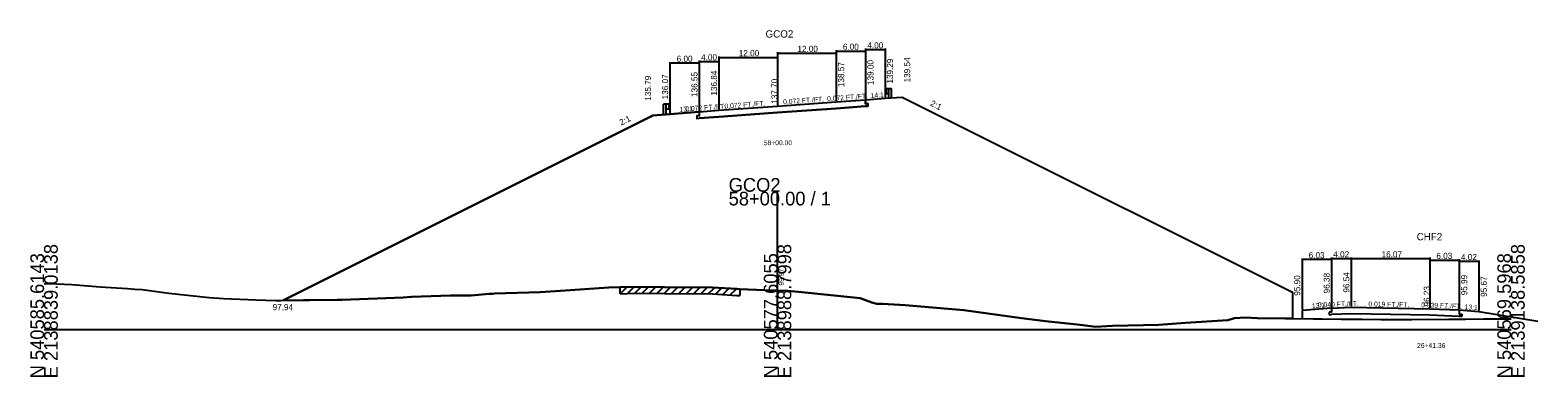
# Model space of a CAD drawing. Extents: x -14327 to 8886, y -10 to 39048.
# Drawn here: x 1997.2 to 2305.5, y 15990.3 to 16061.2 of the extents above; entities that cross this region are included whole.
import ezdxf

# ---------------------------------------------------------------- set-up
doc = ezdxf.new("R2010")
doc.units = 0
for name, color, linetype in [('Level 1', 7, 'Continuous'), ('Level 20', 7, 'Continuous'), ('Level 5', 7, 'Continuous'), ('Level 53', 7, 'Continuous'), ('Level 54', 7, 'Continuous'), ('Level 55', 7, 'Continuous'), ('Level 7', 7, 'Continuous'), ('RD_GPK_XS_Cell', 7, 'Continuous'), ('RD_XS_EwShp', 7, 'Continuous'), ('RD_XS_ExGround', 7, 'Continuous'), ('RD_XS_ExPaveRet', 7, 'Continuous'), ('RD_XS_Pave', 7, 'Continuous'), ('RD_XS_TX_Baseline', 7, 'Continuous'), ('RD_XS_TX_Elev_EX', 7, 'Continuous'), ('RD_XS_TX_Elev_PR', 7, 'Continuous'), ('RD_XS_TX_Station', 7, 'Continuous')]:
    doc.layers.add(name, color=color, linetype=linetype)

msp = doc.modelspace()

# ---------------------------------------------------------------- linework, layer by layer
at = {"layer": 'Level 1'}
for p, q in [((2172.02, 16049.1), (2172.14, 16049.2)), ((2172.02, 16049), (2172.14, 16048.91)), ((2172.02, 16048.57), (2172.14, 16048.67)), ((2172.15, 16049.2), (2172.23, 16049.21)), ((2172.16, 16048.87), (2172.16, 16048.71)), ((2172.23, 16049.27), (2172.23, 16048.3)), ((2172.23, 16049.27), (2172.78, 16049.27)), ((2172.78, 16047.29), (2172.78, 16049.27)), ((2172.78, 16049.27), (2173.34, 16049.27)), ((2173.34, 16047.29), (2173.34, 16049.27)), ((2126.66, 16044.07), (2126.66, 16046.06)), ((2127.22, 16046.06), (2126.66, 16046.06)), ((2127.22, 16044.07), (2127.22, 16046.06)), ((2127.77, 16046.06), (2127.22, 16046.06)), ((2127.77, 16046.06), (2127.77, 16045.09)), ((2127.85, 16045.99), (2127.77, 16046)), ((2127.84, 16045.65), (2127.84, 16045.5)), ((2127.98, 16045.89), (2127.86, 16045.98)), ((2127.98, 16045.79), (2127.86, 16045.7)), ((2127.98, 16045.36), (2127.86, 16045.45)), ((2172.02, 16048.47), (2172.14, 16048.38)), ((2172.15, 16048.38), (2172.23, 16048.36)), ((2172.23, 16048.3), (2172.78, 16048.3)), ((2127.77, 16045.09), (2127.22, 16045.09)), ((2127.85, 16045.16), (2127.77, 16045.15)), ((2127.98, 16045.26), (2127.86, 16045.17))]:
    msp.add_line(p, q, dxfattribs=at)
for centre, radius, start, end in [((2172.07, 16049.05), 0.0651, 129.0336, 230.9663), ((2172.07, 16048.52), 0.0651, 129.0336, 230.9663), ((2172.09, 16048.71), 0.0651, 302.9895, 0), ((2172.15, 16049.18), 0.026, 90, 129.0505), ((2172.09, 16048.87), 0.0651, 0, 45), ((2127.91, 16045.65), 0.0651, 135, 180), ((2127.91, 16045.5), 0.0651, 180, 237.0105), ((2127.85, 16045.96), 0.026, 50.9495, 90), ((2127.93, 16045.84), 0.0651, 309.0337, 50.9664), ((2172.15, 16048.4), 0.026, 230.9496, 270), ((2127.85, 16045.19), 0.026, 270, 309.0504), ((2127.93, 16045.31), 0.0651, 309.0337, 50.9664)]:
    msp.add_arc(centre, radius, start, end, dxfattribs=at)
at = {"layer": 'Level 20'}
for p, q in [((2263.31, 16014.69), (2263.31, 16004.58)), ((2267.33, 16014.69), (2267.33, 16004.74)), ((2283.39, 16014.69), (2283.39, 16004.43)), ((2257.28, 16014.53), (2257.28, 16004.1)), ((2263.31, 16014.33), (2257.28, 16014.33)), ((2263.31, 16014.53), (2263.31, 16004.58)), ((2263.31, 16014.49), (2267.33, 16014.49)), ((2267.33, 16014.49), (2283.39, 16014.49)), ((2283.39, 16014.38), (2283.39, 16004.43)), ((2283.39, 16014.18), (2289.42, 16014.18)), ((2289.42, 16014.38), (2289.42, 16004.19)), ((2289.42, 16014.14), (2289.42, 16004.19)), ((2289.42, 16013.94), (2293.44, 16013.94)), ((2293.44, 16014.14), (2293.44, 16003.87)), ((2263.31, 16004.38), (2257.28, 16003.9)), ((2257.28, 16003.9), (2257.28, 16002.19)), ((2263.31, 16003.54), (2262.81, 16003.52)), ((2262.81, 16003.52), (2262.81, 16003.02)), ((2262.81, 16003.02), (2263.31, 16003.04)), ((2263.31, 16004.38), (2267.33, 16004.54)), ((2263.31, 16004.38), (2263.31, 16003.54)), ((2267.33, 16003.21), (2263.31, 16003.04)), ((2267.33, 16004.54), (2283.39, 16004.23)), ((2283.39, 16002.9), (2267.33, 16003.21)), ((2283.39, 16004.23), (2289.42, 16003.99)), ((2289.42, 16002.66), (2283.39, 16002.9)), ((2289.42, 16003.99), (2289.42, 16003.16)), ((2289.42, 16003.99), (2293.44, 16003.67)), ((2289.42, 16003.16), (2289.92, 16003.14)), ((2289.92, 16002.64), (2289.42, 16002.66)), ((2289.92, 16003.14), (2289.92, 16002.64)), ((2293.44, 16003.67), (2305.49, 16001.67))]:
    msp.add_line(p, q, dxfattribs=at)
at = {"layer": 'Level 5'}
for p, q in [((2168, 16045.67), (2162, 16045.23)), ((2168, 16047), (2168, 16046.17)), ((2168, 16046.17), (2168.5, 16046.2)), ((2168.5, 16045.7), (2168, 16045.67)), ((2168.5, 16046.2), (2168.5, 16045.7)), ((2134, 16043.72), (2133.5, 16043.68)), ((2133.5, 16043.68), (2133.5, 16043.18)), ((2133.5, 16043.18), (2134, 16043.22)), ((2134, 16044.55), (2134, 16043.72)), ((2138, 16043.51), (2134, 16043.22)), ((2150, 16044.37), (2138, 16043.51)), ((2162, 16045.23), (2150, 16044.37))]:
    msp.add_line(p, q, dxfattribs=at)
at = {"layer": 'Level 54'}
for p, q in [((2128, 16054.7), (2128, 16044.27)), ((2134, 16054.99), (2134, 16044.75)), ((2134, 16054.79), (2138, 16054.79)), ((2134, 16054.7), (2134, 16044.75)), ((2138, 16055.85), (2138, 16045.04)), ((2138, 16055.65), (2150, 16055.65)), ((2138, 16054.99), (2138, 16045.04)), ((2150, 16056.72), (2150, 16045.9)), ((2150, 16056.52), (2162, 16056.52)), ((2150, 16055.85), (2150, 16045.9)), ((2162, 16057.15), (2162, 16046.77)), ((2162, 16056.95), (2168, 16056.95)), ((2162, 16056.72), (2162, 16046.77)), ((2168, 16057.44), (2168, 16047.2)), ((2168, 16057.24), (2172, 16057.24)), ((2168, 16057.15), (2168, 16047.2)), ((2172, 16057.44), (2172, 16047.49)), ((2134, 16054.5), (2128, 16054.5))]:
    msp.add_line(p, q, dxfattribs=at)
at = {"layer": 'Level 7'}
for p, q in [((2168, 16047), (2172, 16047.29)), ((2172, 16047.29), (2175.5, 16047.54)), ((2175.5, 16047.54), (2187.5, 16041.54)), ((2124.5, 16043.79), (2112.5, 16037.79)), ((2128, 16044.07), (2124.5, 16043.79)), ((2134, 16044.55), (2128, 16044.07)), ((2187.5, 16041.54), (2255.28, 16007.65)), ((2112.5, 16037.79), (2048.8, 16005.94)), ((2255.28, 16007.65), (2255.28, 16002.21))]:
    msp.add_line(p, q, dxfattribs=at)
at = {"layer": 'RD_GPK_XS_Cell'}
for p, q in [((2150, 16000), (2150, 16028.17)), ((2000, 16000), (2150, 16000)), ((2150, 16000), (2300, 16000))]:
    msp.add_line(p, q, dxfattribs=at)
at = {"layer": 'RD_XS_EwShp'}
msp.add_lwpolyline([(2134, 16044.55), (2134, 16043.72), (2133.5, 16043.68), (2133.5, 16043.18), (2134, 16043.22), (2138, 16043.51), (2150, 16044.37), (2162, 16045.23), (2168, 16045.67), (2168.5, 16045.7), (2168.5, 16046.2), (2168, 16046.17), (2168, 16047), (2172, 16047.29), (2175.5, 16047.54), (2187.5, 16041.54), (2255.28, 16007.65), (2255.28, 16002.21), (2248.11, 16002.28), (2245.69, 16002.45), (2243.42, 16002.33), (2242.06, 16001.91), (2233.44, 16001.35), (2230.73, 16001.17), (2228, 16000.95), (2218.49, 16000.71), (2215, 16000.56), (2214.54, 16000.6), (2211.89, 16000.93), (2204.78, 16001.68), (2199.87, 16002.29), (2188.09, 16003.95), (2176.13, 16004.94), (2171.44, 16005.22), (2170.32, 16005.21), (2169.3, 16005.52), (2168, 16006), (2166.92, 16006.37), (2154.31, 16007.67), (2152.01, 16007.89), (2150, 16007.97), (2147.39, 16008.07), (2142.31, 16008.26), (2141.69, 16008.28), (2136.69, 16008.56), (2126.91, 16008.67), (2120.66, 16008.74), (2117.81, 16008.62), (2115.49, 16008.6), (2105.63, 16007.93), (2101.43, 16007.62), (2092.14, 16007.33), (2091.72, 16007.32), (2091, 16007.28), (2087.37, 16006.98), (2084.75, 16006.96), (2083.13, 16006.97), (2075.14, 16006.66), (2073.41, 16006.56), (2060.96, 16006.07), (2059.94, 16006.06), (2054.31, 16006.02), (2053.03, 16005.98), (2048.8, 16005.94), (2112.5, 16037.79), (2124.5, 16043.79), (2128, 16044.07)], close=True, dxfattribs=at)
at = {"layer": 'RD_XS_ExGround'}
for p, q in [((2000, 16009.39), (2002.61, 16009.32)), ((2002.61, 16009.32), (2005.7, 16009.22)), ((2005.7, 16009.22), (2011.45, 16008.72)), ((2011.45, 16008.72), (2017.05, 16008.37)), ((2105.63, 16007.93), (2115.49, 16008.6)), ((2115.49, 16008.6), (2117.81, 16008.62)), ((2117.81, 16008.62), (2120.66, 16008.74)), ((2120.66, 16008.74), (2126.91, 16008.67)), ((2126.91, 16008.67), (2136.69, 16008.56)), ((2136.69, 16008.56), (2141.69, 16008.28)), ((2017.05, 16008.37), (2018.59, 16008.27)), ((2018.59, 16008.27), (2020.08, 16008.15)), ((2020.08, 16008.15), (2025.51, 16007.42)), ((2025.51, 16007.42), (2033.75, 16006.53)), ((2033.75, 16006.53), (2036.72, 16006.32)), ((2036.72, 16006.32), (2043.3, 16006.07)), ((2043.3, 16006.07), (2047.39, 16005.94)), ((2047.39, 16005.94), (2048.41, 16005.94)), ((2048.41, 16005.94), (2053.03, 16005.98)), ((2053.03, 16005.98), (2054.31, 16006.02)), ((2054.31, 16006.02), (2059.94, 16006.06)), ((2059.94, 16006.06), (2060.96, 16006.07)), ((2060.96, 16006.07), (2073.41, 16006.56)), ((2073.41, 16006.56), (2075.14, 16006.66)), ((2075.14, 16006.66), (2083.13, 16006.97)), ((2083.13, 16006.97), (2084.75, 16006.96)), ((2084.75, 16006.96), (2087.37, 16006.98)), ((2087.37, 16006.98), (2091, 16007.28)), ((2091, 16007.28), (2091.72, 16007.32)), ((2091.72, 16007.32), (2092.14, 16007.33)), ((2092.14, 16007.33), (2101.43, 16007.62)), ((2101.43, 16007.62), (2105.63, 16007.93)), ((2141.69, 16008.28), (2142.31, 16008.26)), ((2142.31, 16008.26), (2147.39, 16008.07)), ((2147.39, 16008.07), (2150, 16007.97)), ((2150, 16007.97), (2152.01, 16007.89)), ((2152.01, 16007.89), (2154.31, 16007.67)), ((2154.31, 16007.67), (2166.92, 16006.37)), ((2166.92, 16006.37), (2168, 16006)), ((2168, 16006), (2169.3, 16005.52)), ((2169.3, 16005.52), (2170.32, 16005.21)), ((2170.32, 16005.21), (2171.44, 16005.22)), ((2171.44, 16005.22), (2176.13, 16004.94)), ((2176.13, 16004.94), (2188.09, 16003.95)), ((2188.09, 16003.95), (2199.87, 16002.29)), ((2199.87, 16002.29), (2204.78, 16001.68)), ((2242.06, 16001.91), (2243.42, 16002.33)), ((2243.42, 16002.33), (2245.69, 16002.45)), ((2245.69, 16002.45), (2248.11, 16002.28)), ((2248.11, 16002.28), (2259.55, 16002.17)), ((2204.78, 16001.68), (2211.89, 16000.93)), ((2211.89, 16000.93), (2214.54, 16000.6)), ((2214.54, 16000.6), (2215, 16000.56)), ((2215, 16000.56), (2218.49, 16000.71)), ((2218.49, 16000.71), (2228, 16000.95)), ((2228, 16000.95), (2230.73, 16001.17)), ((2230.73, 16001.17), (2233.44, 16001.35)), ((2233.44, 16001.35), (2242.06, 16001.91)), ((2259.55, 16002.17), (2261.36, 16002.16)), ((2261.36, 16002.16), (2265.26, 16002.12)), ((2265.26, 16002.12), (2269.53, 16002.1)), ((2269.53, 16002.1), (2273.4, 16002.07)), ((2273.4, 16002.07), (2276.49, 16002.04)), ((2276.49, 16002.04), (2279.75, 16002.05)), ((2279.75, 16002.05), (2287.26, 16002.13)), ((2287.26, 16002.13), (2290.72, 16002.14)), ((2290.72, 16002.14), (2294.43, 16002.17)), ((2294.43, 16002.17), (2297.88, 16002.15)), ((2297.88, 16002.15), (2300, 16002.15))]:
    msp.add_line(p, q, dxfattribs=at)
at = {"layer": 'RD_XS_ExPaveRet'}
for p, q in [((2117.81, 16007.32), (2119.16, 16008.68)), ((2117.81, 16007.32), (2117.81, 16008.62)), ((2119.31, 16007.38), (2120.67, 16008.74)), ((2120.81, 16007.43), (2122.1, 16008.72)), ((2122.31, 16007.42), (2123.6, 16008.71)), ((2123.82, 16007.41), (2125.11, 16008.69)), ((2125.32, 16007.39), (2126.61, 16008.68)), ((2126.82, 16007.38), (2128.11, 16008.66)), ((2128.32, 16007.36), (2129.61, 16008.64)), ((2129.83, 16007.34), (2131.11, 16008.62)), ((2131.33, 16007.32), (2132.62, 16008.61)), ((2132.83, 16007.3), (2134.12, 16008.59)), ((2134.33, 16007.29), (2135.62, 16008.57)), ((2135.84, 16007.27), (2137.1, 16008.54)), ((2137.34, 16007.22), (2138.57, 16008.46)), ((2117.81, 16007.32), (2120.66, 16007.44)), ((2120.66, 16007.44), (2126.91, 16007.37)), ((2126.91, 16007.37), (2136.69, 16007.26)), ((2136.69, 16007.26), (2141.69, 16006.98)), ((2138.84, 16007.14), (2140.07, 16008.37)), ((2140.34, 16007.06), (2141.58, 16008.29)), ((2141.69, 16006.98), (2142.31, 16006.96)), ((2142.31, 16008.26), (2142.31, 16006.96))]:
    msp.add_line(p, q, dxfattribs=at)
at = {"layer": 'RD_XS_Pave'}
for p, q in [((2138, 16044.84), (2150, 16045.7)), ((2150, 16045.7), (2162, 16046.57)), ((2162, 16046.57), (2168, 16047)), ((2134, 16044.55), (2138, 16044.84))]:
    msp.add_line(p, q, dxfattribs=at)

# ---------------------------------------------------------------- texts
at = {"layer": 'Level 20'}
for s, height, p in [('CHF2', 1.5, (2280.71, 16018.23)), ('6.03', 1.25, (2258.62, 16014.58)), ('4.02', 1.25, (2263.65, 16014.74)), ('16.07', 1.25, (2273.53, 16014.74)), ('6.03', 1.25, (2284.73, 16014.43)), ('4.02', 1.25, (2289.76, 16014.19)), ('26+41.36', 1, (2280.78, 15996.23))]:
    msp.add_text(s, height=height, dxfattribs=at).set_placement(p)
for s, height, rotation, p in [('96.54', 1.25, 90, (2266.95, 16007.54)), ('95.90', 1.25, 90, (2256.9, 16006.9)), ('96.38', 1.25, 90, (2262.93, 16007.38)), (' 96.23', 1.25, 90, (2283.39, 16004.23)), ('95.99', 1.25, 90, (2291.05, 16006.99)), ('95.67', 1.25, 90, (2295.07, 16006.67)), ('13:1', 1, 4.5547, (2259.32, 16004.31)), ('0.040 FT./FT.', 1, 2.3104, (2260.54, 16004.52)), ('0.019 FT./FT.', 1, 358.8885, (2270.83, 16004.72)), ('0.039 FT./FT.', 1, 357.7484, (2281.62, 16004.55)), ('13:1', 1, 355.4453, (2290.49, 16004.16))]:
    msp.add_text(s, height=height, rotation=rotation, dxfattribs=at).set_placement(p)
at = {"layer": 'Level 53'}
for s, rotation, p in [('139.00', 90, (2169.63, 16050)), ('139.29', 90, (2173.63, 16050.29)), ('139.54', 90, (2177.13, 16050.54)), ('135.79', 90, (2124.13, 16046.79)), ('136.07', 90, (2127.63, 16047.07)), ('136.55', 90, (2133.63, 16047.55)), ('136.84', 90, (2137.63, 16047.84)), ('138.57', 90, (2163.63, 16049.57)), ('2:1', 333.4349, (2181.11, 16045.85)), ('2:1', 26.5651, (2118.05, 16041.69))]:
    msp.add_text(s, height=1.25, rotation=rotation, dxfattribs=at).set_placement(p)
msp.add_text('97.94', height=1.25, dxfattribs=at).set_placement((2046.74, 16003.94))
at = {"layer": 'Level 54'}
for s, p in [('12.00', (2154.07, 16056.77)), ('6.00', (2163.37, 16057.2)), ('4.00', (2168.37, 16057.49)), ('6.00', (2129.37, 16054.75)), ('4.00', (2134.37, 16055.04)), ('12.00', (2142.07, 16055.9))]:
    msp.add_text(s, height=1.25, dxfattribs=at).set_placement(p)
at = {"layer": 'Level 55'}
for s, rotation, p in [('13:1', 4.5739, (2130.03, 16044.48)), ('0.072 FT./FT.', 4.1182, (2131.18, 16044.6)), ('0.072 FT./FT.', 4.1182, (2139.18, 16045.18)), ('0.072 FT./FT.', 4.1182, (2151.18, 16046.04)), ('0.072 FT./FT.', 4.1182, (2160.18, 16046.69)), ('14:1', 4.1182, (2169.08, 16047.33))]:
    msp.add_text(s, height=1, rotation=rotation, dxfattribs=at).set_placement(p)
at = {"layer": 'RD_GPK_XS_Cell'}
for s, p in [('GCO2', (2140, 16028.17)), ('58+00.00 / 1', (2140, 16025.37))]:
    msp.add_text(s, height=2.8, dxfattribs=at).set_placement(p)
for s, p in [('N 540585.6143', (2000, 15990)), ('E 2138839.0138', (2002.8, 15990)), ('N 540577.6055', (2150, 15990)), ('E 2138988.7998', (2152.8, 15990)), ('N 540569.5968', (2300, 15990)), ('E 2139138.5858', (2302.8, 15990))]:
    msp.add_text(s, height=2.8, rotation=90, dxfattribs=at).set_placement(p)
at = {"layer": 'RD_XS_TX_Baseline'}
msp.add_text('GCO2', height=1.5, dxfattribs=at).set_placement((2147.55, 16059.7))
at = {"layer": 'RD_XS_TX_Elev_EX'}
msp.add_text('99.97', height=1, rotation=90, dxfattribs=at).set_placement((2151.25, 16008.97))
at = {"layer": 'RD_XS_TX_Elev_PR'}
msp.add_text(' 137.70', height=1.25, rotation=90, dxfattribs=at).set_placement((2150, 16045.7))
at = {"layer": 'RD_XS_TX_Station'}
msp.add_text('58+00.00', height=1, dxfattribs=at).set_placement((2147.18, 16037.7))

doc.saveas('drawing.dxf')
